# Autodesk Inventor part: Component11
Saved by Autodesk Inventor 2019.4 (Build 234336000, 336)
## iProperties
Created: 2020-06
Part Number: Component11
Material: Generic
Document SubType Name: Modeling
Designer: Administrator
Density: 1 g/cm^3
Appearance: Default
Title: Component11
Author: Administrator
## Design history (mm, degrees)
